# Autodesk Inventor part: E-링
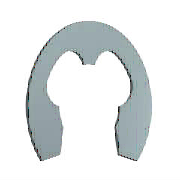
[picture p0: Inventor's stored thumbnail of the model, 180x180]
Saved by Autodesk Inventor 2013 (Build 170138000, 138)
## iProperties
IsCustomPart: 1
Created: 2012-02
Part Number: E-링
Material: 강철, 연강
Description: 일반용 테이퍼 및 줄어든 횡단면 리테이닝 링 - E-링 외부 시리즈 3CM1 리테이닝 링
Document SubType Name: Modeling
Standard: ANSI B27.7
Designer: mduedu
Standard Revision: 1999
Standards Organization: ANSI
Language: ko-KR
Size Designation: 6
Categories: <MemberInstance><Categories><Category DisplayName="샤프트 부품" InternalName="7f7aeb1f-a693-4053-b835-cee3144e0d98" Mnemonic="SHFT"><Category DisplayName="써클립" Inter
Density: 7.86 g/cm^3
Mass: 0.226141 g
Surface Area: 1.26477 cm^2
Volume: 0.0287711 cm^3
Author: mduedu
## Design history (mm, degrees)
sketch "스케치1"
  geometry: L1 (-0.485, 0.024)-(0, 0.024) reference; L2 (-3.206, 0)-(3.486, 0) reference; L3 (-2.223, -3.946)-(2.223, -3.946); L4 (0, 1.949)-(0, -3.479) reference; L5 (-2.91, -2.006)-(-2.435, -2.006); L6 (-0.485, -0.066)-(-0.485, 0.405); L7 (0, 2.574)-(2.53, 2.574); L8 (-2.223, -3.946)-(-3.022, -6.291); L9 (0, -0.551)-(-1.278, -0.551); L10 (2.223, -3.946)-(3.022, -6.291); L11 (2.91, -2.006)-(2.435, -2.006); L12 (0.485, -0.066)-(0.485, 0.405); C1 r 3 at (0, -2.976); A1 r 2.425 centre (0, -2.976) between (-2.297, -2.199) and (-2.223, -3.946); A2 r 0.485 centre (0, -0.066) between (-0.485, -0.066) and (0.485, -0.066); A3 r 5.55 centre (0, -2.976) between (4.27, -6.521) and (-4.27, -6.521); A4 r 3.88 centre (0, -2.976) between (-0.97, 0.78) and (-3.424, -1.15); A5 r 0.388 centre (-0.873, 0.405) between (-0.485, 0.405) and (-0.97, 0.78); A6 r 0.582 centre (-2.91, -1.424) between (-3.424, -1.15) and (-2.91, -2.006); A7 r 0.145 centre (-2.435, -2.152) between (-2.297, -2.199) and (-2.435, -2.006); A8 r 0.727 centre (-3.711, -6.057) between (-4.27, -6.521) and (-3.022, -6.291); A9 r 0.727 centre (3.711, -6.057) between (3.022, -6.291) and (4.27, -6.521); A10 r 2.425 centre (0, -2.976) between (2.223, -3.946) and (2.297, -2.199); A11 r 0.145 centre (2.435, -2.152) between (2.435, -2.006) and (2.297, -2.199); A12 r 0.582 centre (2.91, -1.424) between (2.91, -2.006) and (3.424, -1.15); A13 r 3.88 centre (0, -2.976) between (3.424, -1.15) and (0.97, 0.78); A14 r 0.388 centre (0.873, 0.405) between (0.97, 0.78) and (0.485, 0.405); 1 further point
  constraints: 30 point on circle, 20 end point, 15 centre point, 13 symmetric about line, 12 tangent, 8 point on line, 4 parallel, 2 coincident, 2 horizontal, 1 concentric, 1 perpendicular, 1 vertical alignment, 9 other
  dimensions: "d0" = 6 diameter of C1 (= WD); "d3" = 0.97 distance from line of A1.centre L3 (= 0.2 x ND); "d4" = 0.485 radius of A2 (= 0.1 x ND); "d5" = 11.1 diameter of A3 (= SD2); "d8" = 3.88 radius of A4 (= 0.8 x ND); "d9" = 0.97 distance from line of A1.centre L5 (= 0.2 x ND); "d10" = 0.388 radius of A5 (= 0.08 x ND); "d11" = 0.582 radius of A6 (= 0.12 x ND); "d12" = 0.1455 radius of A7 (= 0.03 x ND); "d13" = 0.7275 radius of A8 (= 0.15 x ND); "d14" = 2.425 distance from line of A1.centre L9 (= 0.5 x ND); "d15" = 2.425 radius of A1 (= 0.5 x ND)
extrude "본체" new body sketch "스케치1" distance "d16" = 0.6 (= SD); taper "d17" = 0 deg
workaxis "Work Axis1"
workaxis "Work Axis2"
workplane "Work Plane1"
body "Solid1"
other parameters: "ND" = 4.85 [user parameter; used in 14 equation terms], "SD" = 0.6 [user parameter; used in 1 equation term], "WD" = 6 (= WDMIN) [user parameter; used in 1 equation term], "d1" = 7.76 (= 1.6 x ND), "d2" = 4.85 (= ND), "SD2" = 11.1 [user parameter; used in 1 equation term], "d6" = 4.85 (= ND), "d7" = 0.7275 (= 0.15 x ND), "d18" = 0, "d19" = 0, "d27" = 0, "d28" = 0, "WDMIN" = 6 [user parameter; used in 1 equation term], "SNB" = 0.7 [user parameter], "WDMAX" = 7 [user parameter], "BUBRMI" = 1.2 [user parameter]
